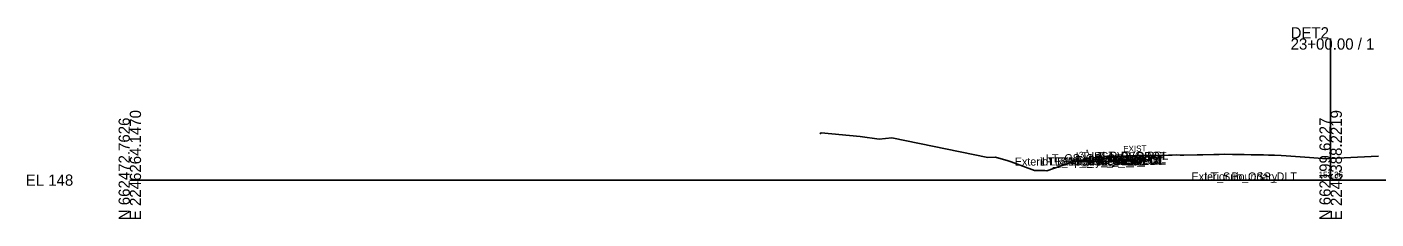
# Model space of a CAD drawing. Extents: x -26 to 603, y -10 to 9526.
# Drawn here: x -25.7 to 311.3, y 5990.3 to 6038.2 of the extents above; entities that cross this region are included whole.
import ezdxf

# ---------------------------------------------------------------- set-up
doc = ezdxf.new("R2010")
doc.units = 0
for name, color, linetype in [('Default', 7, 'Continuous'), ('Exist Cross Section Cell', 7, 'Continuous'), ('Exist XS Center Line Elevation Label', 7, 'Continuous'), ('Exist XS Ground Line', 7, 'Continuous'), ('Prop CMT Pvmt Course 1', 7, 'Continuous'), ('Prop CMT Pvmt Course 2', 7, 'Continuous'), ('Prop CMT Pvmt Course 3', 7, 'Continuous'), ('Prop CMT Pvmt Surface', 7, 'Continuous'), ('Prop CMT Pvmt Surface Shoulder', 7, 'Continuous'), ('Prop CMT Shld Paved Course 1', 7, 'Continuous'), ('Prop CMT Shld Paved Course 2', 7, 'Continuous'), ('Prop CMT Shld Paved Course 3', 7, 'Continuous'), ('Prop CMT Slope Grass', 7, 'Continuous'), ('Prop CMT Subgrade Earthwork', 7, 'Continuous'), ('Prop XS SE Text', 7, 'Continuous'), ('Prop XS Side Slope Text', 7, 'Continuous'), ('Scratch_Level_2', 7, 'Continuous')]:
    doc.layers.add(name, color=color, linetype=linetype)

msp = doc.modelspace()

# ---------------------------------------------------------------- linework, layer by layer
at = {"layer": 'Exist Cross Section Cell'}
for p, q in [((300, 6000), (300, 6035.36)), ((0, 6000), (300, 6000)), ((300, 6000), (600, 6000))]:
    msp.add_line(p, q, dxfattribs=at)
at = {"layer": 'Exist XS Ground Line'}
for p, q in [((172.39, 6011.56), (172.72, 6011.79)), ((172.72, 6011.79), (182.43, 6010.85)), ((182.43, 6010.85), (187.19, 6010.22)), ((187.19, 6010.22), (190.4, 6010.55)), ((190.4, 6010.55), (214.33, 6005.68)), ((236.73, 6004.61), (248.49, 6006.01)), ((248.49, 6006.01), (248.99, 6006.07)), ((248.99, 6006.07), (250.36, 6006.08)), ((250.36, 6006.08), (251.19, 6006.11)), ((251.19, 6006.11), (251.97, 6006.12)), ((251.97, 6006.12), (255.94, 6006.18)), ((255.94, 6006.18), (259.52, 6006.22)), ((259.52, 6006.22), (260.41, 6006.23)), ((260.41, 6006.23), (261.6, 6006.29)), ((261.6, 6006.29), (262.42, 6006.25)), ((262.42, 6006.25), (263.3, 6006.26)), ((263.3, 6006.26), (266.64, 6006.32)), ((266.64, 6006.32), (267.07, 6006.32)), ((267.07, 6006.32), (268.03, 6006.34)), ((268.03, 6006.34), (270.85, 6006.4)), ((270.85, 6006.4), (272.13, 6006.42)), ((272.13, 6006.42), (273.59, 6006.49)), ((273.59, 6006.49), (275.51, 6006.41)), ((275.51, 6006.41), (275.84, 6006.4)), ((275.84, 6006.4), (277.62, 6006.37)), ((277.62, 6006.37), (278.4, 6006.36)), ((278.4, 6006.36), (280.12, 6006.33)), ((280.12, 6006.33), (282.18, 6006.3)), ((282.18, 6006.3), (282.56, 6006.29)), ((282.56, 6006.29), (283.21, 6006.28)), ((283.21, 6006.28), (284.5, 6006.25)), ((284.5, 6006.25), (285.95, 6006.22)), ((285.95, 6006.22), (287.64, 6006.15)), ((287.64, 6006.15), (288.9, 6006.04)), ((288.9, 6006.04), (294.68, 6005.63)), ((300, 6005.36), (310.12, 6005.87)), ((310.12, 6005.87), (311.92, 6005.98)), ((214.33, 6005.68), (216.23, 6005.73)), ((216.23, 6005.73), (219.46, 6004.82)), ((219.46, 6004.82), (220.2, 6004.54)), ((220.2, 6004.54), (225.99, 6002.4)), ((229.11, 6002.36), (234.33, 6004.17)), ((234.33, 6004.17), (234.97, 6004.4)), ((234.97, 6004.4), (235.82, 6004.53)), ((235.82, 6004.53), (236.73, 6004.61)), ((294.68, 6005.63), (299.03, 6005.31)), ((299.03, 6005.31), (300, 6005.36)), ((225.99, 6002.4), (228.56, 6002.38)), ((228.56, 6002.38), (229.11, 6002.36))]:
    msp.add_line(p, q, dxfattribs=at)
at = {"layer": 'Prop CMT Pvmt Course 1'}
for points in [[(251.19, 6006.11), (249.5, 6006.06)], [(249.5, 6006.06), (249.5, 6005.15)], [(251.19, 6005.19), (251.19, 6006.11)], [(249.5, 6005.15), (251.19, 6005.19)]]:
    msp.add_lwpolyline(points, dxfattribs=at)
at = {"layer": 'Prop CMT Pvmt Course 2'}
for points in [[(251.19, 6005.19), (249.5, 6005.15)], [(249.5, 6005.15), (249.5, 6004.81)], [(249.5, 6004.81), (251.19, 6004.86)], [(251.19, 6004.86), (251.19, 6005.19)]]:
    msp.add_lwpolyline(points, dxfattribs=at)
at = {"layer": 'Prop CMT Pvmt Course 3'}
for points in [[(251.19, 6004.86), (249.5, 6004.81)], [(249.5, 6004.81), (251.19, 6004.86)], [(249.5, 6004.81), (249.5, 6004.81)], [(251.19, 6004.86), (251.19, 6004.86)]]:
    msp.add_lwpolyline(points, dxfattribs=at)
at = {"layer": 'Prop CMT Pvmt Surface'}
msp.add_lwpolyline([(251.19, 6006.11), (249.5, 6006.06)], dxfattribs=at)
at = {"layer": 'Prop CMT Pvmt Surface Shoulder'}
msp.add_lwpolyline([(249.5, 6006.06), (245.5, 6005.96)], dxfattribs=at)
at = {"layer": 'Prop CMT Shld Paved Course 1'}
for points in [[(249.5, 6006.06), (245.5, 6005.96), (244.56, 6005.02)], [(249.5, 6005.15), (249.5, 6006.06)], [(244.56, 6005.02), (249.5, 6005.15)]]:
    msp.add_lwpolyline(points, dxfattribs=at)
at = {"layer": 'Prop CMT Shld Paved Course 2'}
for points in [[(249.5, 6005.15), (244.56, 6005.02), (244.22, 6004.68)], [(244.22, 6004.68), (249.5, 6004.81)], [(249.5, 6004.81), (249.5, 6005.15)]]:
    msp.add_lwpolyline(points, dxfattribs=at)
at = {"layer": 'Prop CMT Shld Paved Course 3'}
for points in [[(249.5, 6004.81), (244.22, 6004.68), (243.72, 6004.67)], [(243.72, 6004.67), (249.5, 6004.81)], [(243.72, 6004.67), (243.72, 6004.67)], [(249.5, 6004.81), (249.5, 6004.81)]]:
    msp.add_lwpolyline(points, dxfattribs=at)
at = {"layer": 'Prop CMT Slope Grass'}
msp.add_lwpolyline([(245.5, 6005.96), (239.5, 6005.48), (236.96, 6004.64)], dxfattribs=at)
at = {"layer": 'Prop CMT Subgrade Earthwork'}
for points in [[(243.72, 6004.67), (236.96, 6004.64)], [(249.5, 6004.81), (243.72, 6004.67)], [(251.19, 6004.86), (249.5, 6004.81)]]:
    msp.add_lwpolyline(points, dxfattribs=at)

# ---------------------------------------------------------------- texts
at = {"layer": 'Default'}
msp.add_text('-', height=0.0001, dxfattribs=at).set_placement((0, 6000))
msp.add_text('-', height=0.0001, dxfattribs=at).set_placement((0, 6000))
msp.add_text('-', height=0.0001, dxfattribs=at).set_placement((0, 6000))
msp.add_text('-', height=0.0001, dxfattribs=at).set_placement((0, 6000))
at = {"layer": 'Exist Cross Section Cell'}
for s, p in [('DET2', (290, 6035.36)), ('23+00.00 / 1', (290, 6032.56)), ('EL 148', (-26, 5998.6))]:
    msp.add_text(s, height=2.8, dxfattribs=at).set_placement(p)
for s, p in [('E 2246264.1470', (2.8, 5990)), ('E 2246388.2219', (302.8, 5990)), ('N 662472.7626', (0, 5990)), ('N 662199.6227', (300, 5990))]:
    msp.add_text(s, height=2.8, rotation=90, dxfattribs=at).set_placement(p)
at = {"layer": 'Exist XS Center Line Elevation Label'}
msp.add_text('153.36', height=1.5, dxfattribs=at).set_placement((296.98, 6000.61))
at = {"layer": 'Prop XS SE Text'}
msp.add_text('EXIST', height=1.5, rotation=1.4321, dxfattribs=at).set_placement((248.2, 6007.03))
at = {"layer": 'Prop XS Side Slope Text'}
msp.add_text('3:1', height=1.5, rotation=18.4332, dxfattribs=at).set_placement((237.48, 6005.45))
at = {"layer": 'Scratch_Level_2'}
for s, p in [('LT_Sub_Trench_Out', (227.92, 6003.67)), ('LT_GS_OS_CTL', (228.87, 6004.48)), ('LT_PS3_Shelf_Out', (229.7, 6003.67)), ('LT_PS2_OEOP', (234.8, 6004.02)), ('LT_PS1_OEOP', (236.3, 6004.96)), ('LT_Sub_OEOT', (239.58, 6003.81)), ('LT_PV2_OEOT', (239.67, 6004.15)), ('LT_PV3_OEOT', (239.67, 6003.81)), ('LT_PV1_OEOT', (240.24, 6005.06)), ('LT_Sub_PGL', (242.3, 6003.86)), ('LT_PV2_PGL', (242.4, 6004.19)), ('LT_PV3_PGL', (242.4, 6003.86)), ('LT_PV1_PGL', (242.97, 6005.11)), ('Exterior Boundary', (221.1, 6003.64)), ('LT_Slope_Fill', (227.48, 6003.64)), ('LT_PS3_OEOP', (234.46, 6003.68)), ('Exterior Boundary', (265.25, 5999.92)), ('Exterior Boundary', (265.25, 5999.92)), ('LT_Sub_OSS_DLT', (268.51, 5999.92)), ('LT_Sub_OSS_DLT', (268.51, 5999.92))]:
    msp.add_text(s, height=2, dxfattribs=at).set_placement(p)

doc.saveas('drawing.dxf')
